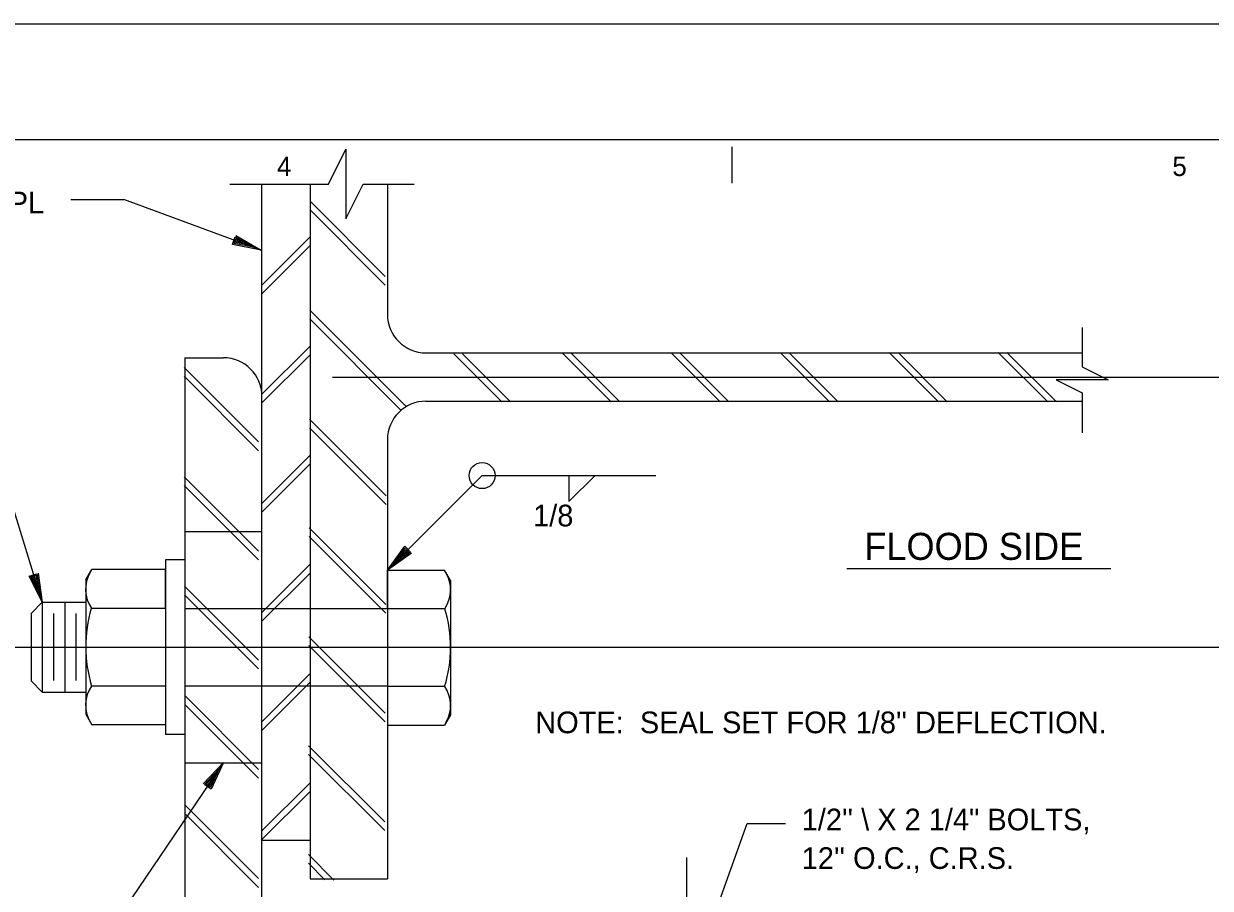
# Model space of a CAD drawing. Extents: x 22371.58 to 22374.41, y 22370.57 to 22372.4.
# Drawn here: x 22373.327 to 22373.968, y 22371.936 to 22372.403 of the extents above; entities that cross this region are included whole.
import ezdxf

# ---------------------------------------------------------------- set-up
doc = ezdxf.new("R2010")
doc.units = 0
for name, color, linetype in [('G-ANNO-SYMB', 7, 'Continuous'), ('G-ANNO-TEXT', 7, 'Continuous'), ('G-ANNO-TTBL', 7, 'Continuous'), ('S-ANNO-DIMS', 7, 'Continuous'), ('S-ANNO-TEXT', 7, 'Continuous'), ('S-GATE-SEAL', 7, 'Continuous'), ('S-SECT-MISC', 7, 'Continuous')]:
    doc.layers.add(name, color=color, linetype=linetype)

msp = doc.modelspace()

# ---------------------------------------------------------------- linework, layer by layer
at = {"layer": 'G-ANNO-SYMB'}
msp.add_lwpolyline([(22371.57831, 22372.40278), (22374.41164, 22372.40278), (22374.41164, 22370.56945), (22371.57831, 22370.56945)], close=True, dxfattribs=at)
at = {"layer": 'G-ANNO-TTBL'}
msp.add_line((22373.70956, 22372.31665), (22373.70956, 22372.33634), dxfattribs=at)
msp.add_lwpolyline([(22371.77622, 22372.34028), (22374.19289, 22372.34028), (22374.19289, 22370.63195), (22371.77622, 22370.63195)], close=True, dxfattribs=at)
msp.add_lwpolyline([(22371.77622, 22372.34028), (22374.19289, 22372.34028), (22374.19289, 22370.63195), (22371.77622, 22370.63195)], close=True, dxfattribs=at)
at = {"layer": 'S-ANNO-DIMS'}
for p, q in [((22373.43841, 22372.31624), (22373.49172, 22372.31624)), ((22373.5104, 22372.31624), (22373.53791, 22372.31624)), ((22373.35255, 22372.30793), (22373.38107, 22372.30793)), ((22373.45525, 22372.2806), (22373.38107, 22372.30793)), ((22373.45118, 22372.2821), (22373.45118, 22372.2821)), ((22373.45525, 22372.2806), (22373.45525, 22372.2806)), ((22373.89841, 22372.23878), (22373.89841, 22372.2176)), ((22373.49375, 22372.21207), (22374.13583, 22372.21207)), ((22373.89841, 22372.20359), (22373.89841, 22372.18192)), ((22373.33712, 22372.0905), (22373.30379, 22372.19787)), ((22373.52357, 22372.10787), (22373.57456, 22372.15886)), ((22373.57456, 22372.15886), (22373.66833, 22372.15886)), ((22373.62143, 22372.15886), (22373.62143, 22372.1448)), ((22373.62143, 22372.1448), (22373.6354, 22372.15877)), ((22373.52663, 22372.11093), (22373.52663, 22372.11093)), ((22373.52357, 22372.10787), (22373.52357, 22372.10787)), ((22373.33584, 22372.09463), (22373.33584, 22372.09463)), ((22373.33712, 22372.0905), (22373.33712, 22372.0905)), ((22373.30512, 22372.06624), (22374.0764, 22372.06624)), ((22373.43491, 22372.00398), (22373.38549, 22371.93085)), ((22373.43249, 22372.00038), (22373.43249, 22372.00038)), ((22373.43491, 22372.00398), (22373.43491, 22372.00398)), ((22373.6993, 22371.92005), (22373.71761, 22371.97098)), ((22373.71761, 22371.97098), (22373.73836, 22371.97098)), ((22373.68487, 22371.95267), (22373.68487, 22371.52103))]:
    msp.add_line(p, q, dxfattribs=at)
for points in [[(22373.49172, 22372.31624), (22373.50103, 22372.33499), (22373.50103, 22372.29753), (22373.5104, 22372.31624)], [(22373.45571, 22372.3159), (22373.45604, 22372.31624)], [(22373.44152, 22372.28841), (22373.45525, 22372.2806), (22373.43974, 22372.28357), (22373.44126, 22372.28771), (22373.45118, 22372.2821), (22373.44064, 22372.28411), (22373.44162, 22372.28678), (22373.44727, 22372.28354), (22373.44156, 22372.28466), (22373.44197, 22372.28577), (22373.44321, 22372.28504)], [(22373.89841, 22372.2176), (22373.91248, 22372.21062), (22373.88438, 22372.21062), (22373.89841, 22372.20359)], [(22373.53641, 22372.11706), (22373.52357, 22372.10787), (22373.53276, 22372.12072), (22373.53588, 22372.11759), (22373.52663, 22372.11093), (22373.53288, 22372.11965), (22373.53488, 22372.11765), (22373.52958, 22372.11388), (22373.533, 22372.1186), (22373.53382, 22372.11777), (22373.53264, 22372.11694)], [(22373.33497, 22372.10614), (22373.33712, 22372.0905), (22373.33004, 22372.10461), (22373.33426, 22372.10592), (22373.33584, 22372.09463), (22373.33103, 22372.10423), (22373.33374, 22372.10506), (22373.3346, 22372.09861), (22373.33202, 22372.10383), (22373.33313, 22372.10418), (22373.33332, 22372.10276)], [(22373.42405, 22371.99251), (22373.43491, 22372.00398), (22373.42833, 22371.98962), (22373.42466, 22371.99209), (22373.43249, 22372.00038), (22373.42801, 22371.99064), (22373.42566, 22371.99223), (22373.43015, 22371.99693), (22373.42769, 22371.99165), (22373.42673, 22371.99231), (22373.42773, 22371.99334)]]:
    msp.add_lwpolyline(points, dxfattribs=at)
msp.add_circle((22373.57456, 22372.15886), 0.00703, dxfattribs=at)
at = {"layer": 'S-ANNO-TEXT'}
msp.add_line((22373.77146, 22372.10877), (22373.914, 22372.10877), dxfattribs=at)
at = {"layer": 'S-GATE-SEAL'}
for p, q in [((22373.45571, 22371.87874), (22373.45571, 22372.31624)), ((22373.48175, 22372.31624), (22373.48175, 22371.94124)), ((22373.52341, 22372.31624), (22373.52341, 22372.24592)), ((22373.54425, 22372.22509), (22373.89841, 22372.22509)), ((22373.41404, 22372.22249), (22373.41404, 22371.80582)), ((22373.41404, 22372.22249), (22373.43487, 22372.22249)), ((22373.54425, 22372.19905), (22373.89841, 22372.19905)), ((22373.52341, 22372.17822), (22373.52341, 22371.94124)), ((22373.45571, 22371.96207), (22373.48175, 22371.96207)), ((22373.48175, 22371.94124), (22373.52341, 22371.94124))]:
    msp.add_line(p, q, dxfattribs=at)
for points in [[(22373.52215, 22372.26174), (22373.48165, 22372.30224)], [(22373.52221, 22372.26639), (22373.48166, 22372.30694)], [(22373.45571, 22372.26168), (22373.48175, 22372.28774)], [(22373.45571, 22372.25698), (22373.48175, 22372.28302)], [(22373.53053, 22372.19444), (22373.4815, 22372.24347)], [(22373.53357, 22372.1961), (22373.48152, 22372.24816)], [(22373.45571, 22372.20277), (22373.48175, 22372.22881)], [(22373.58524, 22372.19865), (22373.5593, 22372.22459)], [(22373.58996, 22372.19865), (22373.564, 22372.2246)], [(22373.64416, 22372.19865), (22373.61807, 22372.22475)], [(22373.64887, 22372.19865), (22373.62277, 22372.22476)], [(22373.70309, 22372.19865), (22373.67684, 22372.2249)], [(22373.7078, 22372.19865), (22373.68154, 22372.22491)], [(22373.76202, 22372.19865), (22373.73561, 22372.22506)], [(22373.76673, 22372.19865), (22373.74031, 22372.22507)], [(22373.82093, 22372.19865), (22373.79437, 22372.22523)], [(22373.82565, 22372.19865), (22373.79907, 22372.22524)], [(22373.87986, 22372.19865), (22373.85314, 22372.22537)], [(22373.88458, 22372.19865), (22373.85784, 22372.22539)], [(22373.45571, 22372.19805), (22373.48175, 22372.22409)], [(22373.45388, 22372.17702), (22373.41364, 22372.21726)], [(22373.45388, 22372.17231), (22373.41365, 22372.21254)], [(22373.52277, 22372.14799), (22373.48136, 22372.18939)], [(22373.52275, 22372.14329), (22373.48135, 22372.18468)], [(22373.45571, 22372.14384), (22373.48175, 22372.16988)], [(22373.45571, 22372.13912), (22373.48175, 22372.16517)], [(22373.45388, 22372.1181), (22373.41378, 22372.15821)], [(22373.45388, 22372.11338), (22373.41379, 22372.15348)], [(22373.52253, 22372.0893), (22373.48122, 22372.13062)], [(22373.52251, 22372.0846), (22373.48121, 22372.12591)], [(22373.45571, 22372.08491), (22373.48175, 22372.11096)], [(22373.45571, 22372.08019), (22373.48175, 22372.10625)], [(22373.45388, 22372.05917), (22373.41391, 22372.09913)], [(22373.45388, 22372.05446), (22373.41392, 22372.09441)], [(22373.5223, 22372.0306), (22373.48106, 22372.07184)], [(22373.52228, 22372.0259), (22373.48105, 22372.06714)], [(22373.45571, 22372.02599), (22373.48176, 22372.05204)], [(22373.45571, 22372.02127), (22373.48176, 22372.04732)], [(22373.45388, 22372.00025), (22373.41405, 22372.04008)], [(22373.45388, 22371.99553), (22373.41407, 22372.03535)], [(22373.52207, 22371.9719), (22373.48091, 22372.01307)], [(22373.52205, 22371.96722), (22373.4809, 22372.00836)], [(22373.45571, 22371.96706), (22373.48175, 22371.9931)], [(22373.45571, 22371.96235), (22373.48175, 22371.98839)], [(22373.45388, 22371.94132), (22373.41419, 22371.98102)], [(22373.45388, 22371.9366), (22373.41419, 22371.97629)], [(22373.49453, 22371.94053), (22373.48076, 22371.95429)], [(22373.48971, 22371.94063), (22373.48076, 22371.94958)]]:
    msp.add_lwpolyline(points, dxfattribs=at)
for centre, start, end in [((22373.54425, 22372.24592), 180, 270), ((22373.43487, 22372.20165), 0, 90), ((22373.54425, 22372.17822), 90, 180)]:
    msp.add_arc(centre, 0.02083, start, end, dxfattribs=at)
at = {"layer": 'S-SECT-MISC'}
for p, q in [((22373.41404, 22372.12874), (22373.45571, 22372.12874)), ((22373.40362, 22372.11333), (22373.40362, 22372.01918)), ((22373.41404, 22372.11333), (22373.40362, 22372.11333)), ((22373.36056, 22372.10252), (22373.36381, 22372.10812)), ((22373.36056, 22372.10252), (22373.36056, 22372.03)), ((22373.40356, 22372.10812), (22373.36381, 22372.10812)), ((22373.40356, 22372.10812), (22373.40356, 22372.02439)), ((22373.40356, 22372.08693), (22373.40356, 22372.10812)), ((22373.52357, 22372.10787), (22373.52357, 22372.02412)), ((22373.52357, 22372.08668), (22373.52357, 22372.10787)), ((22373.52357, 22372.10787), (22373.55426, 22372.10787)), ((22373.55751, 22372.10225), (22373.55426, 22372.10787)), ((22373.55751, 22372.10225), (22373.55751, 22372.02975)), ((22373.33712, 22372.0905), (22373.33106, 22372.08443)), ((22373.33712, 22372.0905), (22373.33712, 22372.042)), ((22373.33712, 22372.0905), (22373.36056, 22372.0905)), ((22373.34925, 22372.0905), (22373.34925, 22372.042)), ((22373.33106, 22372.08443), (22373.33106, 22372.04806)), ((22373.34318, 22372.08437), (22373.34318, 22372.04831)), ((22373.35529, 22372.08437), (22373.35529, 22372.04831)), ((22373.36373, 22372.08723), (22373.40356, 22372.08723)), ((22373.41404, 22372.08707), (22373.52341, 22372.08707)), ((22373.55434, 22372.08698), (22373.52357, 22372.08698)), ((22373.33712, 22372.042), (22373.33106, 22372.04806)), ((22373.36373, 22372.04529), (22373.40356, 22372.04529)), ((22373.41404, 22372.0454), (22373.52341, 22372.0454)), ((22373.55434, 22372.04502), (22373.52357, 22372.04502)), ((22373.33712, 22372.042), (22373.36056, 22372.042)), ((22373.36056, 22372.03), (22373.36381, 22372.02439)), ((22373.55751, 22372.02975), (22373.55426, 22372.02412)), ((22373.40356, 22372.02439), (22373.36381, 22372.02439)), ((22373.41404, 22372.01918), (22373.40362, 22372.01918)), ((22373.52357, 22372.02412), (22373.55426, 22372.02412)), ((22373.41404, 22372.00374), (22373.45571, 22372.00374))]:
    msp.add_line(p, q, dxfattribs=at)
for centre, radius, start, end in [((22373.37871, 22372.09752), 0.01818, 149.71241, 214.51098), ((22373.53936, 22372.09727), 0.01818, 325.48902, 30.28759), ((22373.43329, 22372.06652), 0.07273, 163.50341, 196.98163), ((22373.48478, 22372.06627), 0.07273, 343.01837, 16.49659), ((22373.37871, 22372.03498), 0.01818, 145.48902, 210.28759), ((22373.53936, 22372.03472), 0.01818, 329.71241, 34.51098)]:
    msp.add_arc(centre, radius, start, end, dxfattribs=at)

# ---------------------------------------------------------------- texts
at = {"layer": 'G-ANNO-TEXT'}
for s, p in [('4', (22373.46384, 22372.32059)), ('5', (22373.94718, 22372.32059))]:
    msp.add_text(s, height=0.01042, dxfattribs=at).set_placement(p)
at = {"layer": 'S-ANNO-DIMS'}
for s, height, p in [('1/8', 0.011698, (22373.60207, 22372.13144)), ("NOTE:  SEAL SET FOR 1/8'' DEFLECTION.", 0.0116979, (22373.60323, 22372.01978)), ('1/2\'\' \\ X 2 1/4" BOLTS,', 0.0116979, (22373.74708, 22371.96736)), ("12'' O.C., C.R.S.", 0.0116979, (22373.74708, 22371.94655))]:
    msp.add_text(s, height=height, dxfattribs=at).set_placement(p)
at = {"layer": 'S-ANNO-TEXT'}
for s, height, p in [('SKIN PL', 0.011698, (22373.27817, 22372.30041)), ('FLOOD SIDE', 0.014594, (22373.78084, 22372.11337))]:
    msp.add_text(s, height=height, dxfattribs=at).set_placement(p)

doc.saveas('drawing.dxf')
